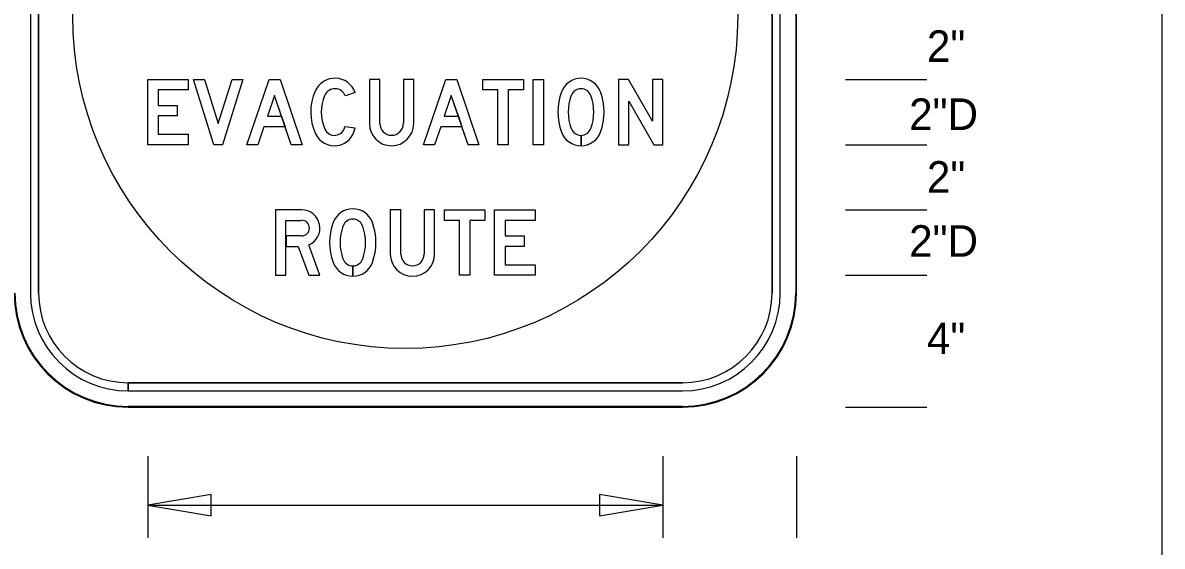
# Model space of a CAD drawing. Extents: x 0 to 770, y 0 to 495.
# Drawn here: x 66.1 to 192.5, y 206.1 to 264.2 of the extents above; entities that cross this region are included whole.
import ezdxf

# ---------------------------------------------------------------- set-up
doc = ezdxf.new("R2010")
doc.units = 0
for name, color, linetype in [('Dimension', 7, 'Continuous'), ('GSBWFill', 7, 'Continuous'), ('GSColorFill', 7, 'Continuous'), ('GSDims', 7, 'Continuous'), ('GSOutline', 7, 'Continuous'), ('IndexDetail_0', 7, 'Continuous'), ('SheetLines_dp', 7, 'Continuous'), ('TextStructures', 7, 'Continuous')]:
    doc.layers.add(name, color=color, linetype=linetype)

msp = doc.modelspace()

# ---------------------------------------------------------------- linework, layer by layer
at = {"layer": 'Dimension'}
for points in [[(79.94, 210.7), (86.96, 209.51), (86.96, 211.88)], [(137.09, 210.7), (130.07, 211.88), (130.07, 209.51)]]:
    msp.add_lwpolyline(points, close=True, dxfattribs=at)
at = {"layer": 'GSBWFill'}
for p, q in [((66.92, 295.7), (66.92, 234.21)), ((67.82, 234.21), (67.82, 295.7)), ((149.21, 295.7), (149.21, 234.21)), ((150.11, 234.21), (150.11, 295.7)), ((151.92, 234.21), (151.92, 295.7)), ((104.53, 257.9), (104.53, 253)), ((102.94, 256.46), (101.86, 256.06)), ((101.8, 252.68), (102.94, 252.51)), ((128.01, 250.54), (128.01, 251.7)), ((128.01, 251.7), (128.01, 250.54)), ((106.85, 243.43), (106.85, 238.53)), ((95.27, 242.27), (97.01, 242.27)), ((102.69, 236.07), (102.69, 237.23)), ((102.69, 237.23), (102.69, 236.07)), ((77.77, 223.36), (77.77, 224.26)), ((139.26, 224.26), (77.78, 224.26)), ((77.78, 224.26), (77.78, 223.36)), ((77.78, 223.36), (139.26, 223.36)), ((77.77, 221.55), (139.26, 221.55))]:
    msp.add_line(p, q, dxfattribs=at)
for points in [[(84.42, 256.74), (81.1, 256.74), (81.1, 255.01), (83.2, 255.01), (83.2, 253.85), (81.1, 253.85), (81.1, 251.82), (84.42, 251.82), (84.42, 250.66), (79.94, 250.66), (79.94, 257.9), (84.42, 257.9)], [(86.22, 257.9), (87.75, 253.02), (89.29, 257.9), (90.5, 257.9), (88.22, 250.66), (87.28, 250.66), (85, 257.9)], [(90.93, 250.66), (93.39, 257.9), (94.62, 257.9), (97.08, 250.66), (95.86, 250.66), (94.01, 256.11), (93.23, 253.81), (94.79, 253.81), (95.18, 252.65), (92.83, 252.65), (92.16, 250.66)], [(110.54, 250.66), (113, 257.9), (114.23, 257.9), (116.69, 250.66), (115.47, 250.66), (113.61, 256.11), (112.83, 253.81), (114.4, 253.81), (114.79, 252.65), (112.44, 252.65), (111.76, 250.66)], [(121.61, 257.9), (121.61, 256.74), (119.94, 256.74), (119.94, 250.66), (118.79, 250.66), (118.79, 256.74), (117.12, 256.74), (117.12, 257.9)], [(122.69, 257.9), (123.85, 257.9), (123.85, 250.66), (122.69, 250.66)], [(137.09, 250.66), (137.09, 257.9), (135.93, 257.9), (135.93, 253.25), (133.28, 257.9), (132.17, 257.9), (132.17, 250.66), (133.33, 250.66), (133.33, 255.48), (136.08, 250.66)], [(117.34, 243.43), (117.34, 242.27), (115.68, 242.27), (115.68, 236.2), (114.52, 236.2), (114.52, 242.27), (112.85, 242.27), (112.85, 243.43)], [(122.91, 242.27), (119.58, 242.27), (119.58, 240.54), (121.69, 240.54), (121.69, 239.38), (119.58, 239.38), (119.58, 237.35), (122.91, 237.35), (122.91, 236.2), (118.42, 236.2), (118.42, 243.43), (122.91, 243.43)]]:
    msp.add_lwpolyline(points, close=True, dxfattribs=at)
for points in [[(105.69, 253), (105.69, 257.9), (104.53, 257.9)], [(109.45, 253), (109.45, 257.9), (108.3, 257.9), (108.3, 253)], [(97.01, 243.43), (94.12, 243.43), (94.12, 236.2), (95.27, 236.2), (95.27, 242.27)], [(108.01, 238.53), (108.01, 243.43), (106.85, 243.43)], [(111.77, 238.53), (111.77, 243.43), (110.61, 243.43), (110.61, 238.53)], [(97.01, 240.54), (95.28, 240.54), (95.28, 239.38), (96.63, 239.38), (97.8, 236.2), (99.04, 236.2), (97.81, 239.54)]]:
    msp.add_lwpolyline(points, dxfattribs=at)
for centre, radius, start, end in [((106.99, 253), 2.46, 180, 0), ((106.99, 253), 1.3, 180, 0), ((97.01, 241.41), 2.03, 293.1324, 90), ((97.01, 241.41), 0.868, 270, 90), ((109.31, 238.53), 2.46, 180, 0), ((109.31, 238.53), 1.3, 180, 0), ((77.77, 234.21), 12.66, 180, 270), ((77.77, 234.21), 10.85, 180, 270), ((77.77, 234.21), 9.95, 180, 270), ((139.26, 234.21), 10.85, 270, 0), ((139.26, 234.21), 9.95, 270, 0), ((139.26, 234.21), 12.66, 270, 0)]:
    msp.add_arc(centre, radius, start, end, dxfattribs=at)
for centre, major_axis, start_param, end_param in [((100.7, 255.64), (0, 2.39), 5.061866, 7.434148), ((128.01, 255.71), (0, 2.31), 5.063177, 7.503193), ((100.7, 255.64), (0, 1.23), 5.061866, 7.434148), ((128.01, 255.71), (0, 1.16), 5.063177, 7.503193), ((103.74, 254.28), (0, 5.72), 1.150963, 2.004476), ((103.74, 254.28), (0, 4.56), 1.150963, 2.004476), ((131.91, 254.28), (0, 6.47), 1.220008, 1.921585), ((131.91, 254.28), (0, 5.32), 1.220008, 1.921585), ((124.11, 254.28), (0, 5.32), 4.361601, 5.063177), ((124.11, 254.28), (0, 6.47), 4.361601, 5.063177), ((100.65, 252.85), (0, 2.31), 2.004476, 4.564141), ((100.65, 252.85), (0, 1.16), 2.004476, 4.564141), ((128.01, 252.85), (0, 2.31), 1.921585, 3.141593), ((128.01, 252.85), (0, 1.16), 1.921585, 3.141593), ((128.01, 252.85), (0, 1.16), 3.141905, 4.361601), ((128.01, 252.85), (0, 2.31), 3.141749, 4.361601), ((102.69, 241.24), (0, 2.31), 5.063177, 7.503193), ((106.59, 239.81), (0, 6.47), 1.220008, 1.921585), ((106.59, 239.81), (0, 5.32), 1.220008, 1.921585), ((102.69, 241.24), (0, 1.16), 5.063177, 7.503193), ((98.79, 239.81), (0, 5.32), 4.361601, 5.063177), ((98.79, 239.81), (0, 6.47), 4.361601, 5.063177), ((102.69, 238.38), (0, 1.16), 1.921585, 3.141593), ((102.69, 238.38), (0, 1.16), 3.141905, 4.361601), ((102.69, 238.38), (0, 2.31), 1.921585, 3.141593), ((102.69, 238.38), (0, 2.31), 3.141749, 4.361601)]:
    msp.add_ellipse(centre, major_axis=major_axis, ratio=0.999993, start_param=start_param, end_param=end_param, dxfattribs=at)
at = {"layer": 'GSColorFill'}
for p, q in [((66.92, 295.7), (66.92, 234.21)), ((67.82, 234.21), (67.82, 295.7)), ((149.21, 295.7), (149.21, 234.21)), ((150.11, 234.21), (150.11, 295.7)), ((151.83, 295.7), (151.83, 234.21)), ((151.92, 234.21), (151.92, 295.7)), ((151.92, 234.21), (151.92, 295.7)), ((104.53, 257.9), (104.53, 253)), ((102.94, 256.46), (101.86, 256.06)), ((101.8, 252.68), (102.94, 252.51)), ((128.01, 250.54), (128.01, 251.7)), ((128.01, 251.7), (128.01, 250.54)), ((106.85, 243.43), (106.85, 238.53)), ((95.27, 242.27), (97.01, 242.27)), ((102.69, 236.07), (102.69, 237.23)), ((102.69, 237.23), (102.69, 236.07)), ((77.77, 223.36), (77.77, 224.26)), ((139.26, 224.26), (77.78, 224.26)), ((77.78, 224.26), (77.78, 223.36)), ((77.78, 223.36), (139.26, 223.36)), ((77.77, 221.55), (77.77, 221.64)), ((139.26, 221.64), (77.77, 221.64)), ((77.77, 221.64), (77.77, 221.55)), ((77.77, 221.55), (139.26, 221.55)), ((77.77, 221.55), (139.26, 221.55))]:
    msp.add_line(p, q, dxfattribs=at)
for points in [[(84.42, 256.74), (81.1, 256.74), (81.1, 255.01), (83.2, 255.01), (83.2, 253.85), (81.1, 253.85), (81.1, 251.82), (84.42, 251.82), (84.42, 250.66), (79.94, 250.66), (79.94, 257.9), (84.42, 257.9)], [(86.22, 257.9), (87.75, 253.02), (89.29, 257.9), (90.5, 257.9), (88.22, 250.66), (87.28, 250.66), (85, 257.9)], [(90.93, 250.66), (93.39, 257.9), (94.62, 257.9), (97.08, 250.66), (95.86, 250.66), (94.01, 256.11), (93.23, 253.81), (94.79, 253.81), (95.18, 252.65), (92.83, 252.65), (92.16, 250.66)], [(110.54, 250.66), (113, 257.9), (114.23, 257.9), (116.69, 250.66), (115.47, 250.66), (113.61, 256.11), (112.83, 253.81), (114.4, 253.81), (114.79, 252.65), (112.44, 252.65), (111.76, 250.66)], [(121.61, 257.9), (121.61, 256.74), (119.94, 256.74), (119.94, 250.66), (118.79, 250.66), (118.79, 256.74), (117.12, 256.74), (117.12, 257.9)], [(122.69, 257.9), (123.85, 257.9), (123.85, 250.66), (122.69, 250.66)], [(137.09, 250.66), (137.09, 257.9), (135.93, 257.9), (135.93, 253.25), (133.28, 257.9), (132.17, 257.9), (132.17, 250.66), (133.33, 250.66), (133.33, 255.48), (136.08, 250.66)], [(117.34, 243.43), (117.34, 242.27), (115.68, 242.27), (115.68, 236.2), (114.52, 236.2), (114.52, 242.27), (112.85, 242.27), (112.85, 243.43)], [(122.91, 242.27), (119.58, 242.27), (119.58, 240.54), (121.69, 240.54), (121.69, 239.38), (119.58, 239.38), (119.58, 237.35), (122.91, 237.35), (122.91, 236.2), (118.42, 236.2), (118.42, 243.43), (122.91, 243.43)]]:
    msp.add_lwpolyline(points, close=True, dxfattribs=at)
for points in [[(105.69, 253), (105.69, 257.9), (104.53, 257.9)], [(109.45, 253), (109.45, 257.9), (108.3, 257.9), (108.3, 253)], [(97.01, 243.43), (94.12, 243.43), (94.12, 236.2), (95.27, 236.2), (95.27, 242.27)], [(108.01, 238.53), (108.01, 243.43), (106.85, 243.43)], [(111.77, 238.53), (111.77, 243.43), (110.61, 243.43), (110.61, 238.53)], [(97.01, 240.54), (95.28, 240.54), (95.28, 239.38), (96.63, 239.38), (97.8, 236.2), (99.04, 236.2), (97.81, 239.54)]]:
    msp.add_lwpolyline(points, dxfattribs=at)
for centre, radius, start, end in [((106.99, 253), 2.46, 180, 0), ((106.99, 253), 1.3, 180, 0), ((97.01, 241.41), 2.03, 293.1324, 90), ((97.01, 241.41), 0.868, 270, 90), ((109.31, 238.53), 2.46, 180, 0), ((109.31, 238.53), 1.3, 180, 0), ((77.77, 234.21), 12.66, 180, 270), ((77.77, 234.21), 12.66, 180, 270), ((77.77, 234.21), 12.57, 180, 270), ((77.77, 234.21), 10.85, 180, 270), ((77.77, 234.21), 9.95, 180, 270), ((139.26, 234.21), 12.66, 270, 0), ((139.26, 234.21), 10.85, 270, 0), ((139.26, 234.21), 9.95, 270, 0), ((139.26, 234.21), 12.66, 270, 0), ((139.26, 234.21), 12.57, 270, 0)]:
    msp.add_arc(centre, radius, start, end, dxfattribs=at)
for centre, major_axis, start_param, end_param in [((100.7, 255.64), (0, 2.39), 5.061866, 7.434148), ((128.01, 255.71), (0, 2.31), 5.063177, 7.503193), ((100.7, 255.64), (0, 1.23), 5.061866, 7.434148), ((128.01, 255.71), (0, 1.16), 5.063177, 7.503193), ((103.74, 254.28), (0, 5.72), 1.150963, 2.004476), ((103.74, 254.28), (0, 4.56), 1.150963, 2.004476), ((131.91, 254.28), (0, 6.47), 1.220008, 1.921585), ((131.91, 254.28), (0, 5.32), 1.220008, 1.921585), ((124.11, 254.28), (0, 5.32), 4.361601, 5.063177), ((124.11, 254.28), (0, 6.47), 4.361601, 5.063177), ((100.65, 252.85), (0, 2.31), 2.004476, 4.564141), ((100.65, 252.85), (0, 1.16), 2.004476, 4.564141), ((128.01, 252.85), (0, 2.31), 1.921585, 3.141593), ((128.01, 252.85), (0, 1.16), 1.921585, 3.141593), ((128.01, 252.85), (0, 1.16), 3.141905, 4.361601), ((128.01, 252.85), (0, 2.31), 3.141749, 4.361601), ((102.69, 241.24), (0, 2.31), 5.063177, 7.503193), ((106.59, 239.81), (0, 6.47), 1.220008, 1.921585), ((106.59, 239.81), (0, 5.32), 1.220008, 1.921585), ((102.69, 241.24), (0, 1.16), 5.063177, 7.503193), ((98.79, 239.81), (0, 5.32), 4.361601, 5.063177), ((98.79, 239.81), (0, 6.47), 4.361601, 5.063177), ((102.69, 238.38), (0, 1.16), 1.921585, 3.141593), ((102.69, 238.38), (0, 1.16), 3.141905, 4.361601), ((102.69, 238.38), (0, 2.31), 1.921585, 3.141593), ((102.69, 238.38), (0, 2.31), 3.141749, 4.361601)]:
    msp.add_ellipse(centre, major_axis=major_axis, ratio=0.999993, start_param=start_param, end_param=end_param, dxfattribs=at)
at = {"layer": 'GSDims'}
for p, q in [((157.35, 257.9), (166.39, 257.9)), ((157.35, 257.9), (166.39, 257.9)), ((157.35, 250.66), (166.39, 250.66)), ((157.35, 250.66), (166.39, 250.66)), ((157.35, 243.43), (166.39, 243.43)), ((157.35, 243.43), (166.39, 243.43)), ((157.35, 236.2), (166.39, 236.2)), ((157.35, 236.2), (166.39, 236.2)), ((157.35, 221.55), (166.39, 221.55)), ((79.94, 216.12), (79.94, 207.08)), ((79.94, 216.12), (79.94, 207.08)), ((137.09, 216.12), (137.09, 207.08)), ((137.09, 216.12), (137.09, 207.08)), ((151.92, 216.12), (151.92, 207.08)), ((79.94, 210.7), (137.09, 210.7))]:
    msp.add_line(p, q, dxfattribs=at)
at = {"layer": 'GSOutline'}
for p, q in [((66.92, 295.7), (66.92, 234.21)), ((67.82, 295.7), (67.82, 234.21)), ((149.21, 234.21), (149.21, 295.7)), ((150.11, 234.21), (150.11, 295.7)), ((151.92, 234.21), (151.92, 295.7)), ((104.53, 257.9), (104.53, 253)), ((102.94, 256.46), (101.86, 256.06)), ((101.8, 252.68), (102.94, 252.51)), ((106.85, 243.43), (106.85, 238.53)), ((99.04, 236.2), (97.81, 239.54)), ((77.77, 224.26), (139.26, 224.26)), ((77.77, 223.36), (139.26, 223.36)), ((77.77, 221.55), (139.26, 221.55))]:
    msp.add_line(p, q, dxfattribs=at)
for points in [[(84.42, 256.74), (81.1, 256.74), (81.1, 255.01), (83.2, 255.01), (83.2, 253.85), (81.1, 253.85), (81.1, 251.82), (84.42, 251.82), (84.42, 250.66), (79.94, 250.66), (79.94, 257.9), (84.42, 257.9)], [(86.22, 257.9), (87.75, 253.02), (89.29, 257.9), (90.5, 257.9), (88.22, 250.66), (87.28, 250.66), (85, 257.9)], [(92.83, 252.65), (92.16, 250.66), (90.93, 250.66), (93.39, 257.9), (94.62, 257.9), (97.08, 250.66), (95.86, 250.66), (95.18, 252.65)], [(112.44, 252.65), (111.76, 250.66), (110.54, 250.66), (113, 257.9), (114.23, 257.9), (116.69, 250.66), (115.47, 250.66), (114.79, 252.65)], [(121.61, 257.9), (121.61, 256.74), (119.94, 256.74), (119.94, 250.66), (118.79, 250.66), (118.79, 256.74), (117.12, 256.74), (117.12, 257.9)], [(122.69, 257.9), (123.85, 257.9), (123.85, 250.66), (122.69, 250.66)], [(137.09, 250.66), (137.09, 257.9), (135.93, 257.9), (135.93, 253.25), (133.28, 257.9), (132.17, 257.9), (132.17, 250.66), (133.33, 250.66), (133.33, 255.48), (136.08, 250.66)], [(93.23, 253.81), (94.79, 253.81), (94.01, 256.11)], [(112.83, 253.81), (114.4, 253.81), (113.61, 256.11)], [(117.34, 243.43), (117.34, 242.27), (115.68, 242.27), (115.68, 236.2), (114.52, 236.2), (114.52, 242.27), (112.85, 242.27), (112.85, 243.43)], [(122.91, 242.27), (119.58, 242.27), (119.58, 240.54), (121.69, 240.54), (121.69, 239.38), (119.58, 239.38), (119.58, 237.35), (122.91, 237.35), (122.91, 236.2), (118.42, 236.2), (118.42, 243.43), (122.91, 243.43)]]:
    msp.add_lwpolyline(points, close=True, dxfattribs=at)
for points in [[(105.69, 253), (105.69, 257.9), (104.53, 257.9)], [(109.45, 253), (109.45, 257.9), (108.3, 257.9), (108.3, 253)], [(97.01, 243.43), (94.12, 243.43), (94.12, 236.2), (95.27, 236.2), (95.27, 239.38), (96.63, 239.38), (97.8, 236.2), (99.04, 236.2)], [(108.01, 238.53), (108.01, 243.43), (106.85, 243.43)], [(111.77, 238.53), (111.77, 243.43), (110.61, 243.43), (110.61, 238.53)], [(97.01, 240.54), (95.27, 240.54), (95.27, 242.27), (97.01, 242.27)]]:
    msp.add_lwpolyline(points, dxfattribs=at)
for centre, radius, start, end in [((106.99, 253), 2.46, 180, 0), ((106.99, 253), 1.3, 180, 0), ((97.01, 241.41), 2.03, 293.1324, 90), ((97.01, 241.41), 0.868, 270, 90), ((109.31, 238.53), 2.46, 180, 0), ((109.31, 238.53), 1.3, 180, 0), ((77.77, 234.21), 12.66, 180, 270), ((77.77, 234.21), 10.85, 180, 270), ((77.77, 234.21), 9.95, 180, 270), ((139.26, 234.21), 10.85, 270, 0), ((139.26, 234.21), 9.95, 270, 0), ((139.26, 234.21), 12.66, 270, 0)]:
    msp.add_arc(centre, radius, start, end, dxfattribs=at)
for centre, major_axis, start_param, end_param in [((100.7, 255.64), (0, 2.39), 5.061866, 7.434148), ((128.01, 255.71), (0, 2.31), 5.063177, 7.503193), ((100.7, 255.64), (0, 1.23), 5.061866, 7.434148), ((128.01, 255.71), (0, 1.16), 5.063177, 7.503193), ((103.74, 254.28), (0, 5.72), 1.150963, 2.004476), ((103.74, 254.28), (0, 4.56), 1.150963, 2.004476), ((131.91, 254.28), (0, 6.47), 1.220008, 1.921585), ((131.91, 254.28), (0, 5.32), 1.220008, 1.921585), ((124.11, 254.28), (0, 5.32), 4.361601, 5.063177), ((124.11, 254.28), (0, 6.47), 4.361601, 5.063177), ((100.65, 252.85), (0, 2.31), 2.004476, 4.564141), ((100.65, 252.85), (0, 1.16), 2.004476, 4.564141), ((128.01, 252.85), (0, 2.31), 1.921585, 4.361601), ((128.01, 252.85), (0, 1.16), 1.921585, 4.361601), ((102.69, 241.24), (0, 2.31), 5.063177, 7.503193), ((106.59, 239.81), (0, 6.47), 1.220008, 1.921585), ((106.59, 239.81), (0, 5.32), 1.220008, 1.921585), ((102.69, 241.24), (0, 1.16), 5.063177, 7.503193), ((98.79, 239.81), (0, 5.32), 4.361601, 5.063177), ((98.79, 239.81), (0, 6.47), 4.361601, 5.063177), ((102.69, 238.38), (0, 1.16), 1.921585, 4.361601), ((102.69, 238.38), (0, 2.31), 1.921585, 4.361601)]:
    msp.add_ellipse(centre, major_axis=major_axis, ratio=0.999993, start_param=start_param, end_param=end_param, dxfattribs=at)
at = {"layer": 'IndexDetail_0'}
msp.add_circle((108.51, 264.95), 36.89, dxfattribs=at)
at = {"layer": 'SheetLines_dp'}
msp.add_line((192.5, 0), (192.5, 495), dxfattribs=at)

# ---------------------------------------------------------------- texts
at = {"layer": 'TextStructures'}
for s, p in [('2"', (166.39, 259.84)), ('2"D', (164.42, 252.29)), ('2"', (166.39, 245.33)), ('2"D', (164.42, 238.23)), ('4"', (166.39, 227.43))]:
    msp.add_text(s, height=3.5, dxfattribs=at).set_placement(p)

doc.saveas('drawing.dxf')
